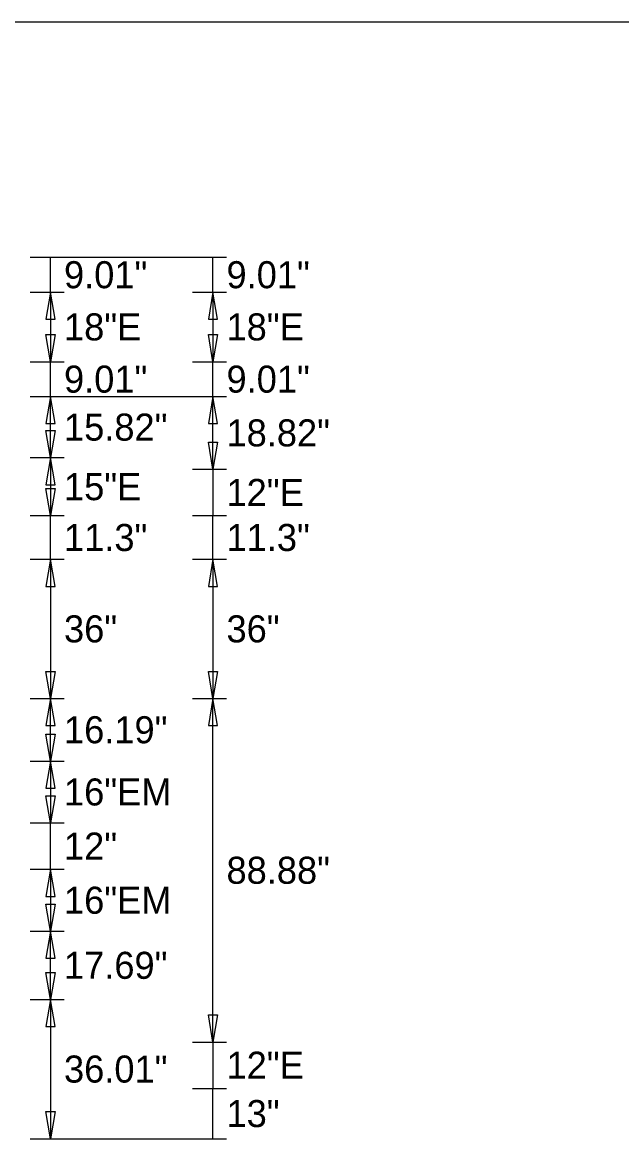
# Model space of a CAD drawing. Extents: x 2149934 to 2150188, y 145113 to 145238.
# Drawn here: x 2150106.34 to 2150119.25, y 145142.88 to 145166.95 of the extents above; entities that cross this region are included whole.
import ezdxf

# ---------------------------------------------------------------- set-up
doc = ezdxf.new("R2010")
doc.units = 0
doc.layers.add('GSDIMS', color=7, linetype='Continuous')
doc.layers.add('Level 1', color=7, linetype='Continuous')

msp = doc.modelspace()

# ---------------------------------------------------------------- linework, layer by layer
at = {"layer": 'GSDIMS'}
for p, q in [((2150106.508, 145161.884), (2150107.237, 145161.884)), ((2150106.508, 145161.884), (2150110.008, 145161.884)), ((2150106.945, 145161.133), (2150106.945, 145161.884)), ((2150110.008, 145161.884), (2150110.737, 145161.884)), ((2150110.445, 145161.133), (2150110.445, 145161.884)), ((2150106.508, 145161.133), (2150107.237, 145161.133)), ((2150106.508, 145161.133), (2150107.237, 145161.133)), ((2150106.945, 145161.133), (2150106.945, 145159.633)), ((2150110.008, 145161.133), (2150110.737, 145161.133)), ((2150110.008, 145161.133), (2150110.737, 145161.133)), ((2150110.445, 145161.133), (2150110.445, 145159.633)), ((2150106.508, 145159.633), (2150107.237, 145159.633)), ((2150106.508, 145159.633), (2150107.237, 145159.633)), ((2150106.945, 145158.883), (2150106.945, 145159.633)), ((2150110.008, 145159.633), (2150110.737, 145159.633)), ((2150110.008, 145159.633), (2150110.737, 145159.633)), ((2150110.445, 145158.883), (2150110.445, 145159.633)), ((2150106.508, 145158.883), (2150107.237, 145158.883)), ((2150106.508, 145158.883), (2150110.008, 145158.883)), ((2150106.508, 145158.883), (2150107.237, 145158.883)), ((2150106.508, 145158.883), (2150110.008, 145158.883)), ((2150106.945, 145157.565), (2150106.945, 145158.883)), ((2150110.008, 145158.883), (2150110.737, 145158.883)), ((2150110.008, 145158.883), (2150110.737, 145158.883)), ((2150110.445, 145157.315), (2150110.445, 145158.883)), ((2150106.508, 145157.565), (2150107.237, 145157.565)), ((2150106.508, 145157.565), (2150107.237, 145157.565)), ((2150106.945, 145157.565), (2150106.945, 145156.315)), ((2150110.008, 145157.315), (2150110.737, 145157.315)), ((2150110.008, 145157.315), (2150110.737, 145157.315)), ((2150110.445, 145157.315), (2150110.445, 145156.315)), ((2150106.508, 145156.315), (2150107.237, 145156.315)), ((2150106.508, 145156.315), (2150107.237, 145156.315)), ((2150106.945, 145155.373), (2150106.945, 145156.315)), ((2150110.008, 145156.315), (2150110.737, 145156.315)), ((2150110.008, 145156.315), (2150110.737, 145156.315)), ((2150110.445, 145155.373), (2150110.445, 145156.315)), ((2150106.508, 145155.373), (2150107.237, 145155.373)), ((2150106.508, 145155.373), (2150107.237, 145155.373)), ((2150106.945, 145155.373), (2150106.945, 145152.373)), ((2150110.008, 145155.373), (2150110.737, 145155.373)), ((2150110.008, 145155.373), (2150110.737, 145155.373)), ((2150110.445, 145155.373), (2150110.445, 145152.373)), ((2150106.508, 145152.373), (2150107.237, 145152.373)), ((2150106.508, 145152.373), (2150107.237, 145152.373)), ((2150106.945, 145151.024), (2150106.945, 145152.373)), ((2150110.008, 145152.373), (2150110.737, 145152.373)), ((2150110.008, 145152.373), (2150110.737, 145152.373)), ((2150110.445, 145144.966), (2150110.445, 145152.373)), ((2150106.508, 145151.024), (2150107.237, 145151.024)), ((2150106.508, 145151.024), (2150107.237, 145151.024)), ((2150106.945, 145151.024), (2150106.945, 145149.691)), ((2150106.508, 145149.691), (2150107.237, 145149.691)), ((2150106.508, 145149.691), (2150107.237, 145149.691)), ((2150106.945, 145148.691), (2150106.945, 145149.691)), ((2150106.508, 145148.691), (2150107.237, 145148.691)), ((2150106.508, 145148.691), (2150107.237, 145148.691)), ((2150106.945, 145148.691), (2150106.945, 145147.357)), ((2150106.508, 145147.357), (2150107.237, 145147.357)), ((2150106.508, 145147.357), (2150107.237, 145147.357)), ((2150106.945, 145145.883), (2150106.945, 145147.357)), ((2150106.508, 145145.883), (2150107.237, 145145.883)), ((2150106.508, 145145.883), (2150107.237, 145145.883)), ((2150106.945, 145145.883), (2150106.945, 145142.883)), ((2150110.008, 145144.966), (2150110.737, 145144.966)), ((2150110.008, 145144.966), (2150110.737, 145144.966)), ((2150110.445, 145144.966), (2150110.445, 145143.966)), ((2150110.008, 145143.966), (2150110.737, 145143.966)), ((2150110.008, 145143.966), (2150110.737, 145143.966)), ((2150110.445, 145142.883), (2150110.445, 145143.966)), ((2150106.508, 145142.883), (2150107.237, 145142.883)), ((2150106.508, 145142.883), (2150110.008, 145142.883)), ((2150110.008, 145142.883), (2150110.737, 145142.883))]:
    msp.add_line(p, q, dxfattribs=at)
for points in [[(2150106.945, 145161.133), (2150106.848, 145160.55), (2150107.043, 145160.55)], [(2150110.445, 145161.133), (2150110.348, 145160.55), (2150110.543, 145160.55)], [(2150106.945, 145159.633), (2150106.848, 145160.217), (2150107.043, 145160.217)], [(2150110.445, 145159.633), (2150110.348, 145160.217), (2150110.543, 145160.217)], [(2150106.945, 145158.883), (2150106.848, 145158.3), (2150107.043, 145158.3)], [(2150110.445, 145158.883), (2150110.348, 145158.3), (2150110.543, 145158.3)], [(2150106.945, 145157.565), (2150106.848, 145158.148), (2150107.043, 145158.148)], [(2150110.445, 145157.315), (2150110.348, 145157.898), (2150110.543, 145157.898)], [(2150106.945, 145157.565), (2150106.848, 145156.982), (2150107.043, 145156.982)], [(2150106.945, 145156.315), (2150106.848, 145156.898), (2150107.043, 145156.898)], [(2150106.945, 145155.373), (2150106.848, 145154.79), (2150107.043, 145154.79)], [(2150110.445, 145155.373), (2150110.348, 145154.79), (2150110.543, 145154.79)], [(2150106.945, 145152.373), (2150106.848, 145152.957), (2150107.043, 145152.957)], [(2150110.445, 145152.373), (2150110.348, 145152.957), (2150110.543, 145152.957)], [(2150106.945, 145152.373), (2150106.848, 145151.79), (2150107.043, 145151.79)], [(2150110.445, 145152.373), (2150110.348, 145151.79), (2150110.543, 145151.79)], [(2150106.945, 145151.024), (2150106.848, 145151.607), (2150107.043, 145151.607)], [(2150106.945, 145151.024), (2150106.848, 145150.441), (2150107.043, 145150.441)], [(2150106.945, 145149.691), (2150106.848, 145150.274), (2150107.043, 145150.274)], [(2150106.945, 145148.691), (2150106.848, 145148.107), (2150107.043, 145148.107)], [(2150106.945, 145147.357), (2150106.848, 145147.941), (2150107.043, 145147.941)], [(2150106.945, 145147.357), (2150106.848, 145146.774), (2150107.043, 145146.774)], [(2150106.945, 145145.883), (2150106.848, 145146.467), (2150107.043, 145146.467)], [(2150106.945, 145145.883), (2150106.848, 145145.3), (2150107.043, 145145.3)], [(2150110.445, 145144.966), (2150110.348, 145145.55), (2150110.543, 145145.55)], [(2150106.945, 145142.883), (2150106.848, 145143.466), (2150107.043, 145143.466)]]:
    msp.add_lwpolyline(points, close=True, dxfattribs=at)
at = {"layer": 'Level 1'}
msp.add_line((2150135.447, 145166.95), (2150017.557, 145166.95), dxfattribs=at)

# ---------------------------------------------------------------- texts
at = {"layer": 'GSDIMS'}
for s, p in [('9.01"', (2150107.237, 145161.217)), ('9.01"', (2150110.737, 145161.217)), ('18"E', (2150107.237, 145160.092)), ('18"E', (2150110.737, 145160.092)), ('9.01"', (2150107.237, 145158.966)), ('9.01"', (2150110.737, 145158.966)), ('15.82"', (2150107.237, 145157.932)), ('18.82"', (2150110.737, 145157.807)), ('15"E', (2150107.237, 145156.648)), ('12"E', (2150110.737, 145156.523)), ('11.3"', (2150107.237, 145155.552)), ('11.3"', (2150110.737, 145155.552)), ('36"', (2150107.237, 145153.582)), ('36"', (2150110.737, 145153.582)), ('16.19"', (2150107.237, 145151.407)), ('16"EM', (2150107.237, 145150.066)), ('12"', (2150107.237, 145148.899)), ('88.88"', (2150110.737, 145148.378)), ('16"EM', (2150107.237, 145147.732)), ('17.69"', (2150107.237, 145146.329)), ('36.01"', (2150107.237, 145144.092)), ('12"E', (2150110.737, 145144.175)), ('13"', (2150110.737, 145143.133))]:
    msp.add_text(s, height=0.5833, dxfattribs=at).set_placement(p)

doc.saveas('drawing.dxf')
